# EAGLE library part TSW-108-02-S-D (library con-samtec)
THROUGH-HOLE .025" SQ POST HEADER Source: Samtec TSW.pdf
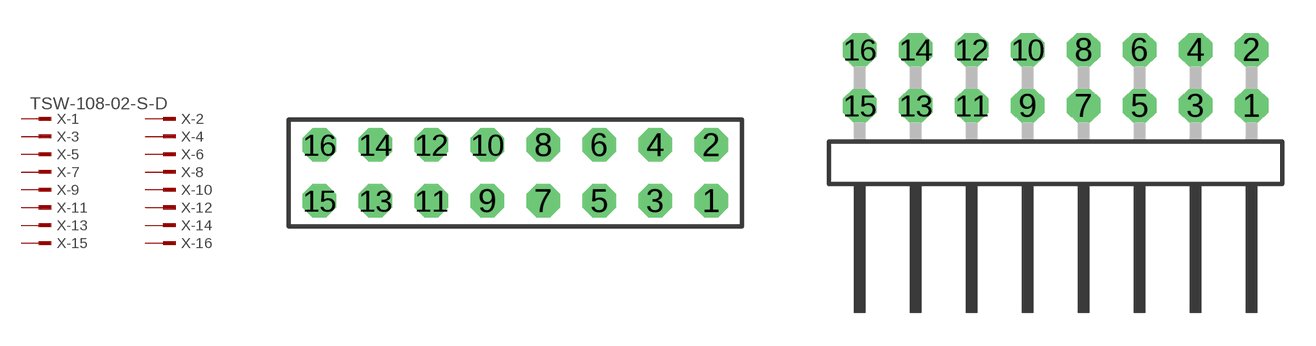
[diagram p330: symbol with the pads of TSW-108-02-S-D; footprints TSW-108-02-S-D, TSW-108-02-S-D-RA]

Designator prefix X; gates -1=MPINV -2=MPIN -3=MPIN -4=MPIN -5=MPIN -6=MPIN -7=MPIN -8=MPIN -9=MPIN -10=MPIN -11=MPIN -12=MPIN -13=MPIN -14=MPIN -15=MPIN -16=MPIN

## TSW-108-02-S-D (OC_FARNELL: unknown; OC_NEWARK: unknown)  [TSW-108-02-S-D]
1  -1:1  pas
2  -2:1  pas
3  -3:1  pas
4  -4:1  pas
5  -5:1  pas
6  -6:1  pas
7  -7:1  pas
8  -8:1  pas
9  -9:1  pas
10  -10:1  pas
11  -11:1  pas
12  -12:1  pas
13  -13:1  pas
14  -14:1  pas
15  -15:1  pas
16  -16:1  pas

## TSW-108-02-S-D-RA (OC_FARNELL: unknown; OC_NEWARK: unknown)  [TSW-108-02-S-D-RA]
Pads as for TSW-108-02-S-D

## Footprint TSW-108-02-S-D (pad centres in mm)
THROUGH-HOLE .025" SQ POST HEADER Source: Samtec TSW.pdf
drill 1 pad 1.5 octagon: 1 8.89,-1.27; 2 8.89,1.27; 3 6.35,-1.27; 4 6.35,1.27; 5 3.81,-1.27; 6 3.81,1.27; 7 1.27,-1.27; 8 1.27,1.27; 9 -1.27,-1.27; 10 -1.27,1.27; 11 -3.81,-1.27; 12 -3.81,1.27; 13 -6.35,-1.27; 14 -6.35,1.27; 15 -8.89,-1.27; 16 -8.89,1.27

## Footprint TSW-108-02-S-D-RA (pad centres in mm)
THROUGH-HOLE .025" SQ POST HEADER Source: Samtec TSW.pdf
drill 1 pad 1.5 octagon: 1 8.89,1.524; 2 8.89,4.064; 3 6.35,1.524; 4 6.35,4.064; 5 3.81,1.524; 6 3.81,4.064; 7 1.27,1.524; 8 1.27,4.064; 9 -1.27,1.524; 10 -1.27,4.064; 11 -3.81,1.524; 12 -3.81,4.064; 13 -6.35,1.524; 14 -6.35,4.064; 15 -8.89,1.524; 16 -8.89,4.064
